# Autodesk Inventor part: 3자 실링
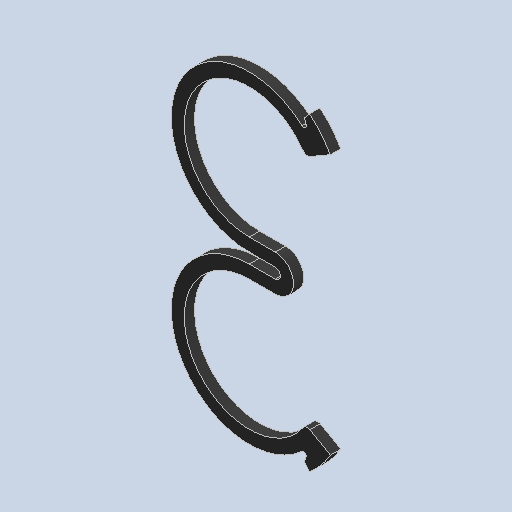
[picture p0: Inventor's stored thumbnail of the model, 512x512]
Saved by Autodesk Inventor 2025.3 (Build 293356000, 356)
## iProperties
Created: 2025-10
Part Number: 3자 실링
Material: 고무
Document SubType Name: Modeling
Designer: PC-15
Density: 0.93 g/cm^3
Appearance: 기본값
Author: jhkim
Sending System: Autodesk Inventor 2026
Preprocessor: ST-DEVELOPER v20.1
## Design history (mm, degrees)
feature "솔리드1"
node "솔리드2"
